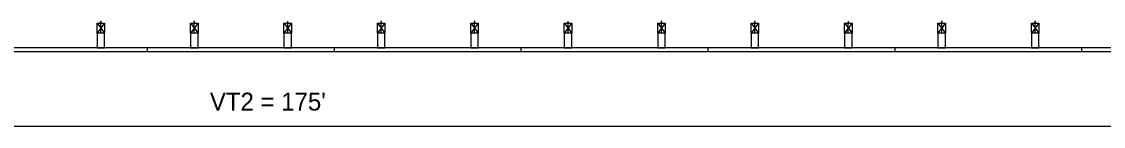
# Model space of a CAD drawing. Extents: x 16537443 to 16538473, y 7054586 to 7055469.
# Drawn here: x 16537812.8 to 16537885.2, y 7054749.6 to 7054756.7 of the extents above; entities that cross this region are included whole.
import ezdxf

# ---------------------------------------------------------------- set-up
doc = ezdxf.new("R2010")
doc.units = 0
doc.layers.add('Draft_DNC', color=7, linetype='Continuous')

msp = doc.modelspace()

# ---------------------------------------------------------------- linework, layer by layer
at = {"layer": 'Draft_DNC'}
for p, q in [((16537818.365, 7054756.553), (16537817.865, 7054755.886)), ((16537817.865, 7054756.553), (16537818.365, 7054755.886)), ((16537818.115, 7054756.65), (16537818.115, 7054756.657)), ((16537818.115, 7054755.886), (16537818.115, 7054756.553)), ((16537824.615, 7054756.553), (16537824.115, 7054755.886)), ((16537824.115, 7054756.553), (16537824.615, 7054755.886)), ((16537824.365, 7054756.65), (16537824.365, 7054756.657)), ((16537824.365, 7054755.886), (16537824.365, 7054756.553)), ((16537830.865, 7054756.553), (16537830.365, 7054755.886)), ((16537830.365, 7054756.553), (16537830.865, 7054755.886)), ((16537830.615, 7054756.65), (16537830.615, 7054756.657)), ((16537830.615, 7054755.886), (16537830.615, 7054756.553)), ((16537837.115, 7054756.553), (16537836.615, 7054755.886)), ((16537836.615, 7054756.553), (16537837.115, 7054755.886)), ((16537836.865, 7054756.65), (16537836.865, 7054756.657)), ((16537836.865, 7054755.886), (16537836.865, 7054756.553)), ((16537843.365, 7054756.553), (16537842.865, 7054755.886)), ((16537842.865, 7054756.553), (16537843.365, 7054755.886)), ((16537843.115, 7054756.65), (16537843.115, 7054756.657)), ((16537843.115, 7054755.886), (16537843.115, 7054756.553)), ((16537849.615, 7054756.553), (16537849.115, 7054755.886)), ((16537849.115, 7054756.553), (16537849.615, 7054755.886)), ((16537849.365, 7054756.65), (16537849.365, 7054756.657)), ((16537849.365, 7054755.886), (16537849.365, 7054756.553)), ((16537855.865, 7054756.553), (16537855.365, 7054755.886)), ((16537855.365, 7054756.553), (16537855.865, 7054755.886)), ((16537855.615, 7054756.65), (16537855.615, 7054756.657)), ((16537855.615, 7054755.886), (16537855.615, 7054756.553)), ((16537862.115, 7054756.553), (16537861.615, 7054755.886)), ((16537861.615, 7054756.553), (16537862.115, 7054755.886)), ((16537861.865, 7054756.65), (16537861.865, 7054756.657)), ((16537861.865, 7054755.886), (16537861.865, 7054756.553)), ((16537868.365, 7054756.553), (16537867.865, 7054755.886)), ((16537867.865, 7054756.553), (16537868.365, 7054755.886)), ((16537868.115, 7054756.65), (16537868.115, 7054756.657)), ((16537868.115, 7054755.886), (16537868.115, 7054756.553)), ((16537874.615, 7054756.553), (16537874.115, 7054755.886)), ((16537874.115, 7054756.553), (16537874.615, 7054755.886)), ((16537874.365, 7054756.65), (16537874.365, 7054756.657)), ((16537874.365, 7054755.886), (16537874.365, 7054756.553)), ((16537880.865, 7054756.553), (16537880.365, 7054755.886)), ((16537880.365, 7054756.553), (16537880.865, 7054755.886)), ((16537880.615, 7054756.65), (16537880.615, 7054756.657)), ((16537880.615, 7054755.886), (16537880.615, 7054756.553)), ((16537818.365, 7054755.886), (16537817.864, 7054755.886)), ((16537817.864, 7054755.886), (16537817.864, 7054754.885)), ((16537818.365, 7054754.885), (16537818.365, 7054755.886)), ((16537824.615, 7054755.886), (16537824.114, 7054755.886)), ((16537824.114, 7054755.886), (16537824.114, 7054754.885)), ((16537824.615, 7054754.885), (16537824.615, 7054755.886)), ((16537830.865, 7054755.886), (16537830.364, 7054755.886)), ((16537830.364, 7054755.886), (16537830.364, 7054754.885)), ((16537830.865, 7054754.885), (16537830.865, 7054755.886)), ((16537837.115, 7054755.886), (16537836.614, 7054755.886)), ((16537836.614, 7054755.886), (16537836.614, 7054754.885)), ((16537837.115, 7054754.885), (16537837.115, 7054755.886)), ((16537843.365, 7054755.886), (16537842.864, 7054755.886)), ((16537842.864, 7054755.886), (16537842.864, 7054754.885)), ((16537843.365, 7054754.885), (16537843.365, 7054755.886)), ((16537849.615, 7054755.886), (16537849.114, 7054755.886)), ((16537849.114, 7054755.886), (16537849.114, 7054754.885)), ((16537849.615, 7054754.885), (16537849.615, 7054755.886)), ((16537855.865, 7054755.886), (16537855.364, 7054755.886)), ((16537855.364, 7054755.886), (16537855.364, 7054754.885)), ((16537855.865, 7054754.885), (16537855.865, 7054755.886)), ((16537862.115, 7054755.886), (16537861.614, 7054755.886)), ((16537861.614, 7054755.886), (16537861.614, 7054754.885)), ((16537862.115, 7054754.885), (16537862.115, 7054755.886)), ((16537868.365, 7054755.886), (16537867.864, 7054755.886)), ((16537867.864, 7054755.886), (16537867.864, 7054754.885)), ((16537868.365, 7054754.885), (16537868.365, 7054755.886)), ((16537874.615, 7054755.886), (16537874.114, 7054755.886)), ((16537874.114, 7054755.886), (16537874.114, 7054754.885)), ((16537874.615, 7054754.885), (16537874.615, 7054755.886)), ((16537880.865, 7054755.886), (16537880.364, 7054755.886)), ((16537880.364, 7054755.886), (16537880.364, 7054754.885)), ((16537880.865, 7054754.885), (16537880.865, 7054755.886)), ((16537821.24, 7054754.885), (16537808.74, 7054754.885)), ((16537821.24, 7054754.615), (16537808.74, 7054754.615)), ((16537817.864, 7054754.885), (16537818.365, 7054754.885)), ((16537821.24, 7054754.615), (16537821.24, 7054754.885)), ((16537833.74, 7054754.885), (16537821.24, 7054754.885)), ((16537821.24, 7054754.615), (16537821.24, 7054754.885)), ((16537833.74, 7054754.615), (16537821.24, 7054754.615)), ((16537824.114, 7054754.885), (16537824.615, 7054754.885)), ((16537830.364, 7054754.885), (16537830.865, 7054754.885)), ((16537833.74, 7054754.615), (16537833.74, 7054754.885)), ((16537846.24, 7054754.885), (16537833.74, 7054754.885)), ((16537833.74, 7054754.615), (16537833.74, 7054754.885)), ((16537846.24, 7054754.615), (16537833.74, 7054754.615)), ((16537836.614, 7054754.885), (16537837.115, 7054754.885)), ((16537842.864, 7054754.885), (16537843.365, 7054754.885)), ((16537846.24, 7054754.615), (16537846.24, 7054754.885)), ((16537858.74, 7054754.885), (16537846.24, 7054754.885)), ((16537846.24, 7054754.615), (16537846.24, 7054754.885)), ((16537858.74, 7054754.615), (16537846.24, 7054754.615)), ((16537849.114, 7054754.885), (16537849.615, 7054754.885)), ((16537855.364, 7054754.885), (16537855.865, 7054754.885)), ((16537858.74, 7054754.615), (16537858.74, 7054754.885)), ((16537871.24, 7054754.885), (16537858.74, 7054754.885)), ((16537858.74, 7054754.615), (16537858.74, 7054754.885)), ((16537871.24, 7054754.615), (16537858.74, 7054754.615)), ((16537861.614, 7054754.885), (16537862.115, 7054754.885)), ((16537867.864, 7054754.885), (16537868.365, 7054754.885)), ((16537871.24, 7054754.615), (16537871.24, 7054754.885)), ((16537883.74, 7054754.885), (16537871.24, 7054754.885)), ((16537871.24, 7054754.615), (16537871.24, 7054754.885)), ((16537883.74, 7054754.615), (16537871.24, 7054754.615)), ((16537874.114, 7054754.885), (16537874.615, 7054754.885)), ((16537880.364, 7054754.885), (16537880.865, 7054754.885)), ((16537883.74, 7054754.615), (16537883.74, 7054754.885)), ((16537896.24, 7054754.885), (16537883.74, 7054754.885)), ((16537883.74, 7054754.615), (16537883.74, 7054754.885)), ((16537896.24, 7054754.615), (16537883.74, 7054754.615)), ((16537905.615, 7054749.616), (16537755.615, 7054749.616))]:
    msp.add_line(p, q, dxfattribs=at)
for points in [[(16537818.365, 7054755.886), (16537817.865, 7054755.886), (16537817.865, 7054756.553), (16537818.365, 7054756.553)], [(16537824.615, 7054755.886), (16537824.115, 7054755.886), (16537824.115, 7054756.553), (16537824.615, 7054756.553)], [(16537830.865, 7054755.886), (16537830.365, 7054755.886), (16537830.365, 7054756.553), (16537830.865, 7054756.553)], [(16537837.115, 7054755.886), (16537836.615, 7054755.886), (16537836.615, 7054756.553), (16537837.115, 7054756.553)], [(16537843.365, 7054755.886), (16537842.865, 7054755.886), (16537842.865, 7054756.553), (16537843.365, 7054756.553)], [(16537849.615, 7054755.886), (16537849.115, 7054755.886), (16537849.115, 7054756.553), (16537849.615, 7054756.553)], [(16537855.865, 7054755.886), (16537855.365, 7054755.886), (16537855.365, 7054756.553), (16537855.865, 7054756.553)], [(16537862.115, 7054755.886), (16537861.615, 7054755.886), (16537861.615, 7054756.553), (16537862.115, 7054756.553)], [(16537868.365, 7054755.886), (16537867.865, 7054755.886), (16537867.865, 7054756.553), (16537868.365, 7054756.553)], [(16537874.615, 7054755.886), (16537874.115, 7054755.886), (16537874.115, 7054756.553), (16537874.615, 7054756.553)], [(16537880.865, 7054755.886), (16537880.365, 7054755.886), (16537880.365, 7054756.553), (16537880.865, 7054756.553)]]:
    msp.add_lwpolyline(points, close=True, dxfattribs=at)
for points in [[(16537818.148, 7054756.553), (16537818.148, 7054756.596), (16537818.081, 7054756.596), (16537818.081, 7054756.553)], [(16537818.134, 7054756.596), (16537818.134, 7054756.65), (16537818.095, 7054756.65), (16537818.095, 7054756.596)], [(16537824.398, 7054756.553), (16537824.398, 7054756.596), (16537824.331, 7054756.596), (16537824.331, 7054756.553)], [(16537824.384, 7054756.596), (16537824.384, 7054756.65), (16537824.345, 7054756.65), (16537824.345, 7054756.596)], [(16537830.648, 7054756.553), (16537830.648, 7054756.596), (16537830.581, 7054756.596), (16537830.581, 7054756.553)], [(16537830.634, 7054756.596), (16537830.634, 7054756.65), (16537830.595, 7054756.65), (16537830.595, 7054756.596)], [(16537836.898, 7054756.553), (16537836.898, 7054756.596), (16537836.831, 7054756.596), (16537836.831, 7054756.553)], [(16537836.884, 7054756.596), (16537836.884, 7054756.65), (16537836.845, 7054756.65), (16537836.845, 7054756.596)], [(16537843.148, 7054756.553), (16537843.148, 7054756.596), (16537843.081, 7054756.596), (16537843.081, 7054756.553)], [(16537843.134, 7054756.596), (16537843.134, 7054756.65), (16537843.095, 7054756.65), (16537843.095, 7054756.596)], [(16537849.398, 7054756.553), (16537849.398, 7054756.596), (16537849.331, 7054756.596), (16537849.331, 7054756.553)], [(16537849.384, 7054756.596), (16537849.384, 7054756.65), (16537849.345, 7054756.65), (16537849.345, 7054756.596)], [(16537855.648, 7054756.553), (16537855.648, 7054756.596), (16537855.581, 7054756.596), (16537855.581, 7054756.553)], [(16537855.634, 7054756.596), (16537855.634, 7054756.65), (16537855.595, 7054756.65), (16537855.595, 7054756.596)], [(16537861.898, 7054756.553), (16537861.898, 7054756.596), (16537861.831, 7054756.596), (16537861.831, 7054756.553)], [(16537861.884, 7054756.596), (16537861.884, 7054756.65), (16537861.845, 7054756.65), (16537861.845, 7054756.596)], [(16537868.148, 7054756.553), (16537868.148, 7054756.596), (16537868.081, 7054756.596), (16537868.081, 7054756.553)], [(16537868.134, 7054756.596), (16537868.134, 7054756.65), (16537868.095, 7054756.65), (16537868.095, 7054756.596)], [(16537874.398, 7054756.553), (16537874.398, 7054756.596), (16537874.331, 7054756.596), (16537874.331, 7054756.553)], [(16537874.384, 7054756.596), (16537874.384, 7054756.65), (16537874.345, 7054756.65), (16537874.345, 7054756.596)], [(16537880.648, 7054756.553), (16537880.648, 7054756.596), (16537880.581, 7054756.596), (16537880.581, 7054756.553)], [(16537880.634, 7054756.596), (16537880.634, 7054756.65), (16537880.595, 7054756.65), (16537880.595, 7054756.596)]]:
    msp.add_lwpolyline(points, dxfattribs=at)

# ---------------------------------------------------------------- texts
msp.add_text("VT2 = 175'", height=1.2, rotation=0.00101, dxfattribs=at).set_placement((16537825.409, 7054750.683))

doc.saveas('drawing.dxf')
